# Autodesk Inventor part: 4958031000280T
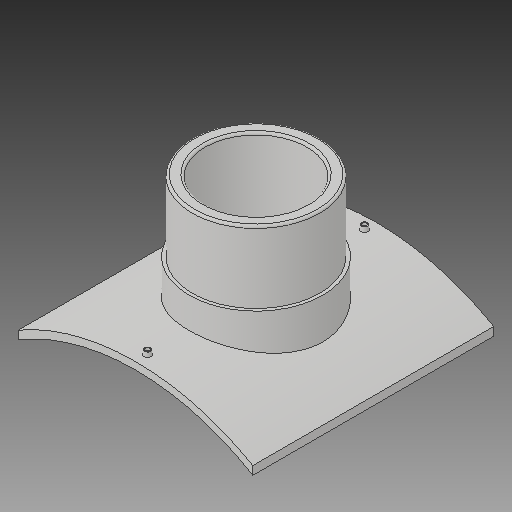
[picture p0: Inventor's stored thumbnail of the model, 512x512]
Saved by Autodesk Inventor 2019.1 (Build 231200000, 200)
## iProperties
Created: 2017-10
Part Number: 4958031000280T
Material: Generic
Description: PLASSON BRANCH SADDLE  1000x280
Document SubType Name: Modeling
Designer: KIM
Mass: 2754.05 g
Surface Area: 3037.44 cm^2
Volume: 2754.05 cm^3
Density: 1 g/cm^3
Appearance: Default
Author: KIM
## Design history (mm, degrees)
derived "495803.ipt"
feature "Solid1::495803.ipt"
tag "TaggingFeature1"
body "Solid1"
other parameters: "d1" = 16, "d2" = 516, "d4" = 0, "d12" = 525.6, "d13" = 14, "d14" = 238.5, "d16" = 5 deg, "d18" = 4, "d19" = 14, "d20" = 0, "d21" = 3, "d22" = 0, "d23" = 741, "d24" = 294, "d25" = 16, "d26" = 224, "d28" = 0, "d29" = 9.6, "d31" = 0, "d32" = 112.5, "d33" = 0, "d37" = 157.5, "d38" = 0, "d39" = 5, "B_" = 516, "H_" = 225, "x_" = 16, "D_" = 16
